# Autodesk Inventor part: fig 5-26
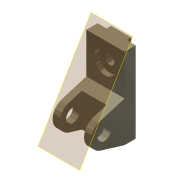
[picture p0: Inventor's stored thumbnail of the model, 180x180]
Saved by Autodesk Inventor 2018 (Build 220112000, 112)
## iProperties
Shininess: 65.0
Angle Display Precision: 2
Document Length Units: 11269
Document Angle Units: 11279
Document Time Units: 11290
Document Mass Units: 11283
Document Length Units Precision: 3
Document Angle Units Precision: 2
Compacted: False
Created: 2001-11
Part Number: fig 5-26
Document SubType Name: Modeling
Designer: Renu Muthoo
Density: 1 g/cm^3
Material: Generic
Appearance: Metal-Titanium (Polished)
Density: 0.0
Volumn: 0.0
Area: 0.0
PropertySet Name: Model Information
Control State: 0
Master: False
Checked Out: False
Author: Renu Muthoo
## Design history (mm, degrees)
node "Sketch1"
sketch "Sketch2"
  geometry: L1 (33.257, 104.664)-(33.257, -75.336); L2 (33.257, -75.336)-(8.257, -75.336); L3 (8.257, -75.336)-(-45.451, -59.045); L4 (-45.451, -1.628)-(8.257, 14.664); L5 (8.257, 14.664)-(8.257, 104.664); L6 (8.257, 104.664)-(33.257, 104.664); C1 r 15 at (-36.743, -30.336); A1 r 30 centre (-36.743, -30.336) between (-45.451, -1.628) and (-45.451, -59.045)
  constraints: 12 end point, 2 centre point, 2 equal length, 2 parallel, 2 point on circle, 2 tangent, 1 coincident, 1 perpendicular, 1 vertical
  dimensions: "d0" = 180 distance of L1.start L1.end; "d1" = 30 radius of A1; "d2" = 25 distance of L5.end L1.start; "d3" = 45 distance from line of L2 A1.centre; "d4" = 70 distance from line of L1 A1.centre; "d5" = 30 diameter of C1
extrude "Extrusion1" new body sketch "Sketch2" distance "d6" = 85; taper "d7" = 0 deg
workplane "Work Plane1"
sketch "Sketch3"
  geometry: L1 (15, 62.364)-(70, 62.364); L2 (70, 62.364)-(70, -52.386); L3 (70, -52.386)-(15, -52.386); L4 (15, -52.386)-(15, 62.364); L5 (0, -45)-(0, -28.708) reference
  constraints: 8 end point, 2 parallel, 1 horizontal, 1 perpendicular
  dimensions: "d8" = 55 distance of L1.start L1.end; "d9" = 15 distance between parallel lines of L5 L4
extrude "Extrusion2" cut sketch "Sketch3" distance "d10" = 50; taper "d11" = 0 deg
sketch "Sketch4"
  geometry: L1 (0, 25)-(85, 25) reference; L2 (0, 0)-(0, 25) reference; L3 (20, 25)-(65, 25); L4 (65, 25)-(65, 35); L5 (65, 35)-(20, 35); L6 (20, 35)-(20, 25)
  constraints: 8 end point, 2 parallel, 1 horizontal, 1 perpendicular, 1 point on line
  dimensions: "d12" = 45 distance of L4.end L5.end; "d13" = 10 distance of L3.end L4.end; "d14" = 20 distance between parallel lines of L2 L6
extrude "Extrusion3" join sketch "Sketch4" stored distance "d15" = 50; taper "d16" = 0 deg
sketch "Sketch5"
  geometry: L1 (85, 0)-(85, 90) reference; L2 (0, 90)-(85, 90) reference; 1 further point
  dimensions: "d17" = 42 distance from line of L2 point (42.5, 48); "d18" = 42.5 distance from line of L1 point (42.5, 48)
hole "Hole1" sketch "Sketch5" at (42.5, 48) diameter "d19" = 20; stored, may be unused: countersink angle "d23" = 82 deg, drill point angle "d25" = 118 deg; dims "d20" = 6, "d21" = 50, "d22" = 10, "d24" = 8
workplane "Work Plane12"
body "Solid1"
